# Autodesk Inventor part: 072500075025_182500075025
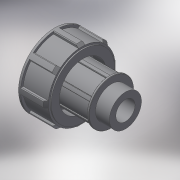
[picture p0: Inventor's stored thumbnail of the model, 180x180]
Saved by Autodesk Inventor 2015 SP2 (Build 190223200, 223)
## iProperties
Created: 2017-04
Part Number: 072500075025_182500075025
Material: Generic
Description: PLASSON THREADED ADAPTOR 75-2.1/2"
Document SubType Name: Modeling
Designer: KIM
Density: 1 g/cm^3
Appearance: Default
Author: KIM
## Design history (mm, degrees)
derived "07250.ipt"
feature "Solid1::07250.ipt"
tag "TaggingFeature1"
body "Solid1"
other parameters: "d1" = 75.184, "d2" = 134, "d3" = 29, "d6" = 132, "d7" = 122.76, "d8" = 105.6, "d9" = 75, "d10" = 90.2208, "d12" = 45.1104, "d13" = 60.1472, "d14" = 33.35, "d15" = 99, "d16" = 4.02, "d17" = 53.6, "d18" = 29, "d19" = 34.8, "d24" = 15.0368, "d25" = 7.5184, "d27" = 0, "d28" = 6.01472, "d31" = 1.50368, "d35" = 360 deg, "d41" = 29.337, "d56" = 82.5, "d57" = 7.5, "d58" = 3.75, "d60" = 0, "d61" = 0.75184, "d64" = 0.75184, "d68" = 360 deg, "d_" = 75, "R_" = 75.184, "E_" = 132, "H_" = 134, "l_2" = 29, "d55" = 75
